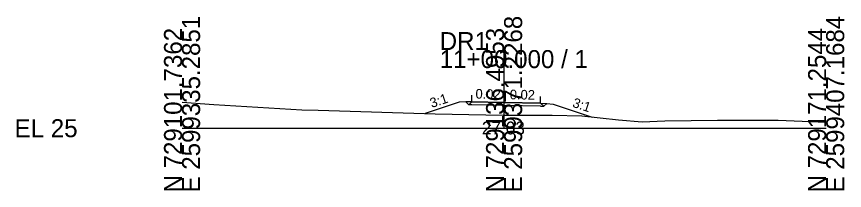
# Model space of a CAD drawing. Extents: x -26 to 1162, y -10 to 9515.
# Drawn here: x -25.7 to 102.8, y 4990.3 to 5017.4 of the extents above; entities that cross this region are included whole.
import ezdxf

# ---------------------------------------------------------------- set-up
doc = ezdxf.new("R2010")
doc.units = 0
for name, color, linetype in [('Exist Cross Section Cell', 7, 'Continuous'), ('Exist XS Center Line Elevation Label', 7, 'Continuous'), ('Exist XS Ground Line', 7, 'Continuous'), ('Prop XS Ditch Slope Text', 7, 'Continuous'), ('Prop XS Dump Level', 7, 'Continuous'), ('Prop XS EOT Tick Mark', 7, 'Continuous'), ('Prop XS Finish Grade', 7, 'Continuous'), ('Prop XS Finish Grade Earthwork', 7, 'Continuous'), ('Prop XS Finish Grade Pavement', 7, 'Continuous'), ('Prop XS Pvmt Edge Slope', 7, 'Continuous'), ('Prop XS SE Text', 7, 'Continuous'), ('Prop XS Subgrade Earthwork', 7, 'Continuous')]:
    doc.layers.add(name, color=color, linetype=linetype)

msp = doc.modelspace()

# ---------------------------------------------------------------- linework, layer by layer
at = {"layer": 'Exist Cross Section Cell'}
for p, q in [((50, 5000), (50, 5012.15)), ((0, 5000), (50, 5000)), ((50, 5000), (100, 5000))]:
    msp.add_line(p, q, dxfattribs=at)
at = {"layer": 'Exist XS Ground Line'}
msp.add_lwpolyline([(0, 5004.05), (4.92, 5003.69), (18.62, 5002.88), (21.13, 5002.82), (39.3, 5002.24), (47.14, 5002.08), (49.83, 5002.03), (57.48, 5002.01), (62.08, 5001.92), (67.76, 5001.28), (71.44, 5001), (74.96, 5001.12), (83.15, 5001.27), (92.54, 5001.25), (100, 5000.96)], dxfattribs=at)
at = {"layer": 'Prop XS Dump Level'}
for p, q in [((50, 5004.02), (45, 5004.12)), ((45, 5004.12), (50, 5004.02)), ((55.63, 5003.91), (50, 5004.02)), ((50, 5004.02), (55.63, 5003.91))]:
    msp.add_line(p, q, dxfattribs=at)
at = {"layer": 'Prop XS EOT Tick Mark'}
for p, q in [((45, 5004.12), (45, 5005.12)), ((55.63, 5003.91), (55.63, 5004.91))]:
    msp.add_line(p, q, dxfattribs=at)
at = {"layer": 'Prop XS Finish Grade'}
for p, q in [((45, 5004.12), (44.06, 5004.08)), ((55.63, 5003.91), (56.62, 5003.83))]:
    msp.add_line(p, q, dxfattribs=at)
at = {"layer": 'Prop XS Finish Grade Earthwork'}
for p, q in [((43, 5004.04), (37.75, 5002.29)), ((44.06, 5004.08), (43, 5004.04)), ((56.62, 5003.83), (57.64, 5003.75)), ((57.64, 5003.75), (63.66, 5001.74))]:
    msp.add_line(p, q, dxfattribs=at)
at = {"layer": 'Prop XS Finish Grade Pavement'}
for p, q in [((45, 5004.12), (50, 5004.02)), ((50, 5004.02), (55.63, 5003.91))]:
    msp.add_line(p, q, dxfattribs=at)
at = {"layer": 'Prop XS Pvmt Edge Slope'}
for p, q in [((44.06, 5004.08), (44.51, 5003.63)), ((45, 5004.12), (44.51, 5003.63)), ((55.63, 5003.91), (56.15, 5003.4)), ((56.62, 5003.83), (56.15, 5003.4))]:
    msp.add_line(p, q, dxfattribs=at)
at = {"layer": 'Prop XS Subgrade Earthwork'}
for p, q in [((44.51, 5003.63), (44.06, 5004.08)), ((44.51, 5003.63), (44.06, 5004.08)), ((56.15, 5003.4), (56.62, 5003.83)), ((56.15, 5003.4), (56.62, 5003.83)), ((45, 5003.62), (44.51, 5003.63)), ((50, 5003.52), (45, 5003.62)), ((55.63, 5003.41), (50, 5003.52)), ((55.63, 5003.41), (56.15, 5003.4))]:
    msp.add_line(p, q, dxfattribs=at)

# ---------------------------------------------------------------- texts
at = {"layer": 'Exist Cross Section Cell'}
for s, p in [('E 2599335.2851', (2.8, 4990)), ('E 2599371.2268', (52.8, 4990)), ('E 2599407.1684', (102.8, 4990)), ('N 729101.7362', (0, 4990)), ('N 729136.4953', (50, 4990)), ('N 729171.2544', (100, 4990))]:
    msp.add_text(s, height=2.8, rotation=90, dxfattribs=at).set_placement(p)
for s, p in [('DR1', (40, 5012.15)), ('11+00.000 / 1', (40, 5009.35)), ('EL 25', (-26, 4998.6))]:
    msp.add_text(s, height=2.8, dxfattribs=at).set_placement(p)
at = {"layer": 'Exist XS Center Line Elevation Label'}
msp.add_text('27.03', height=2, dxfattribs=at).set_placement((46.54, 4999.03))
at = {"layer": 'Prop XS Ditch Slope Text'}
for rotation, p in [(18.4349, (38.77, 5003.14)), (341.5883, (60.51, 5003.34))]:
    msp.add_text('3:1', height=1.5, rotation=rotation, dxfattribs=at).set_placement(p)
at = {"layer": 'Prop XS Dump Level'}
for p in [(43, 5004), (57.64, 5003.71)]:
    msp.add_text('Case1', height=0.04, dxfattribs=at).set_placement(p)
at = {"layer": 'Prop XS SE Text'}
for p in [(45.55, 5004.61), (50.87, 5004.5)]:
    msp.add_text('0.02', height=1.5, rotation=358.8542, dxfattribs=at).set_placement(p)

doc.saveas('drawing.dxf')
